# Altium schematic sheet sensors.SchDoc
size A4
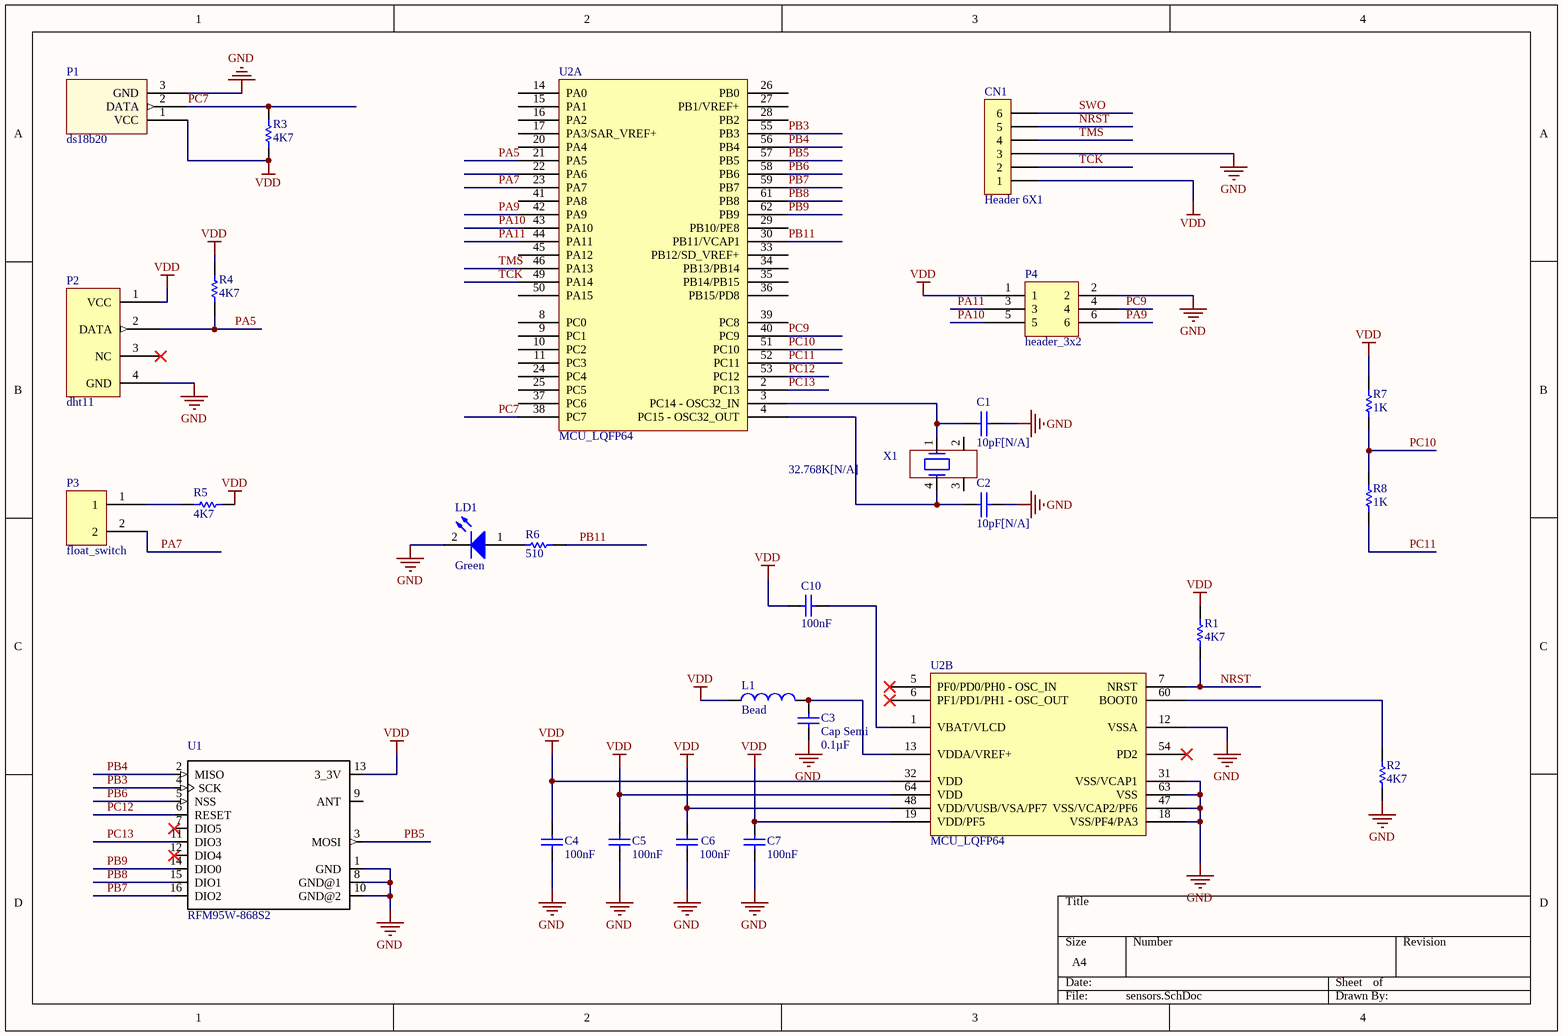
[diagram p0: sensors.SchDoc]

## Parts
C1  10pF[N/A]  [0603C]
C2  10pF[N/A]  [0603C]
C3  Cap Semi  value 0.1µF  [1608[0603]]
C4  100nF  [0603C]
C5  100nF  [0603C]
C6  100nF  [0603C]
C7  100nF  [0603C]
C10  100nF  [0603C]
CN1  Header 6X1  [1*6P]
L1  Bead  [INDC1608L]
LD1  Green  [0603D]
P1  ds18b20  [ds18b20]
P2  dht11  [dht11]
P3  float_switch  [float_switch]
P4  header_3x2  [header_3x2]
R1  4K7  [0603R]
R2  4K7  [0603R]
R3  4K7  [0603R]
R4  4K7  [0603R]
R5  4K7  [0603R]
R6  510  [0603R]
R7  1K  [0603R]
R8  1K  [0603R]
U1  RFM95W-868S2  [XCVR_RFM95W-868S2]
U2  MCU_LQFP64  [LQFP64]  (parts A,B of 2)
X1  32.768K[N/A]  [XTAL_4SM_8X3R8]

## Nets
GND: C1.2 C2.2 C3.2 C4.2 C5.2 C6.2 C7.2 CN1.3 LD1.2(K) P1.3(GND) P2.4(GND) P4.2 R2.1 U1.1(GND) U1.8(GND@1) U1.10(GND@2) U2.12(VSSA) U2.18(VSS/PF4/PA3) U2.31(VSS/VCAP1) U2.47(VSS/VCAP2/PF6) U2.63(VSS)
VDD: C4.1 C5.1 C6.1 C7.1 C10.1 CN1.1 L1.1 P1.1(VCC) P2.1(VCC) P4.1 R1.2 R3.2 R4.1 R5.1 R7.1 U1.13(3_3V) U2.19(VDD/PF5) U2.32(VDD) U2.48(VDD/VUSB/VSA/PF7) U2.64(VDD)
NRST: CN1.5 R1.1 U2.7(NRST)
PA5: P2.2(DATA) R4.2 U2.21(PA5)
PA7: P3.2 U2.23(PA7)
PA9: P4.6 U2.42(PA9)
PA10: P4.5 U2.43(PA10)
PA11: P4.3 U2.44(PA11)
PB3: U1.4(SCK) U2.55(PB3)
PB4: U1.2(MISO) U2.56(PB4)
PB5: U1.3(MOSI) U2.57(PB5)
PB6: U1.5(NSS) U2.58(PB6)
PB7: U1.16(DIO2) U2.59(PB7)
PB8: U1.15(DIO1) U2.61(PB8)
PB9: U1.14(DIO0) U2.62(PB9)
PB11: R6.1 U2.30(PB11/VCAP1)
PC7: P1.2(DATA) R3.1 U2.38(PC7)
PC9: P4.4 U2.40(PC9)
PC10: R7.2 R8.1 U2.51(PC10)
PC11: R8.2 U2.52(PC11)
PC12: U1.6(RESET) U2.53(PC12)
PC13: U1.11(DIO3) U2.2(PC13)
SWO: CN1.6
TCK: CN1.2 U2.49(PA14)
TMS: CN1.4 U2.46(PA13)
NetC1_1: C1.1 U2.3(PC14_-_OSC32_IN) X1.1
NetC2_1: C2.1 U2.4(PC15_-_OSC32_OUT) X1.4
NetC3_1: C3.1 L1.2 U2.13(VDDA/VREF+)
NetC10_2: C10.2 U2.1(VBAT/VLCD)
NetLD1_1: LD1.1(A) R6.2
NetP3_1: P3.1 R5.2
NetR2_2: R2.2 U2.60(BOOT0)

Not connected (* = marked no-connect by the designer): P2 3(NC)*; U1 7(DIO5)* 9(ANT) 12(DIO4)*; U2 5(PF0/PD0/PH0_-_OSC_IN)* 6(PF1/PD1/PH1_-_OSC_OUT)* 8(PC0) 9(PC1) 10(PC2) 11(PC3) 14(PA0) 15(PA1) 16(PA2) 17(PA3/SAR_VREF+) 20(PA4) 22(PA6) 24(PC4) 25(PC5) 26(PB0) 27(PB1/VREF+) 28(PB2) 29(PB10/PE8) 33(PB12/SD_VREF+) 34(PB13/PB14) 35(PB14/PB15) 36(PB15/PD8) 37(PC6) 39(PC8) 41(PA8) 45(PA12) 50(PA15) 54(PD2)*; X1 2 3

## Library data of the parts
C1 = Cap: Capacitor; Manufacturer: Murata Electronics North America; ProductNumber: GRM1885C1H100JA01D; Value: 10pF; Vendor name: Digikey; Vendor PN: 490-1403-1-ND
C2 = CAP: Capacitor; Manufacturer: Murata Electronics North America; ProductNumber: GRM1885C1H100JA01D; Value: 10pF; Vendor name: Digikey; Vendor PN: 490-1403-1-ND
C3 = Cap Semi: Capacitor (Semiconductor SIM Model); Manufacturer: AVX Corporation; ProductNumber: C1608X5R1H104K080AA; Vendor name: Digikey; Vendor PN: 478-6206-1-ND
C4-C6 C10 = Cap: Capacitor; Manufacturer: AVX Corporation; Value: 0.1µF; ProductNumber: C1608X5R1H104K080AA; Vendor name: Digikey; Vendor PN: 478-6206-1-ND
C7 = Cap: Capacitor; Manufacturer: AVX Corporation; Value: 0.1uF; ProductNumber: 06035D104KAT2A; Vendor name: Digikey; Vendor PN: 478-6206-1-ND
CN1 = Header 6X1: Header, 6-Pin, Single row; Manufacturer: Molex; ProductNumber: 0022232061; Vendor name: Digikey; Vendor PN: WM4204-ND
L1 = Inductor: Manufacturer: Taiyo Yuden; Code_IEC: 1005; Value: 600 OHM; ProductNumber: BK1608HS601-T; Vendor name: Digikey; Vendor PN: 587-1874-1-ND
LD1 = LED2: Typical RED, GREEN, YELLOW, AMBER GaAs LED; Manufacturer: Lite-On; ProductNumber: LTST-C190KGKT; Value: 571nm; Vendor name: Digikey; Vendor PN: 160-1435-1-ND
P1 = ds18b20: Manufacturer: Wurth Electronics; ProductNumber: 61300311121; Vendor name: Digikey; Vendor PN: 732-5316-ND
P3 = float_switch: Manufacturer: Harwin Inc.; ProductNumber: M20-9990246; Vendor name: Digikey; Vendor PN: 952-2262-ND
P4 = header_3x2: Manufacturer: Amphenol FCI; ProductNumber: 20021111-00006T4LF; Vendor name: Digikey; Vendor PN: 609-3710-ND
R1-R5 = Res1: Resistor; Manufacturer: Yageo; Value: 4.7 kOhms; ProductNumber: RC0603JR-074K7L; Vendor name: Digikey; Vendor PN: 311-4.7KGRCT-ND
R6 = Res1: Resistor; Manufacturer: Rohm Semiconductor; Value: 510 Ohms; ProductNumber: ESR03EZPJ511; Vendor name: Digikey; Vendor PN: RHM510DCT-ND
R7 R8 = Res1: Resistor; Manufacturer: Susumu; Value: 1 kOhm; ProductNumber: RR0816P-102-D; Vendor name: Digikey; Vendor PN: RR08P1.0KDCT-ND
U1 = RFM95W-868S2: Manufacturer: RF Solutions; MF: Hope Microelectronics; Vendor name: Digikey; Vendor PN: RFM95W-868S2-ND
U2 = MCU_LQFP64: Manufacturer: STM; ProductNumber: STM32L476RGT6; Vendor name: Mouser; Vendor PN: 511-STM32L476RGT6
X1 = MC306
